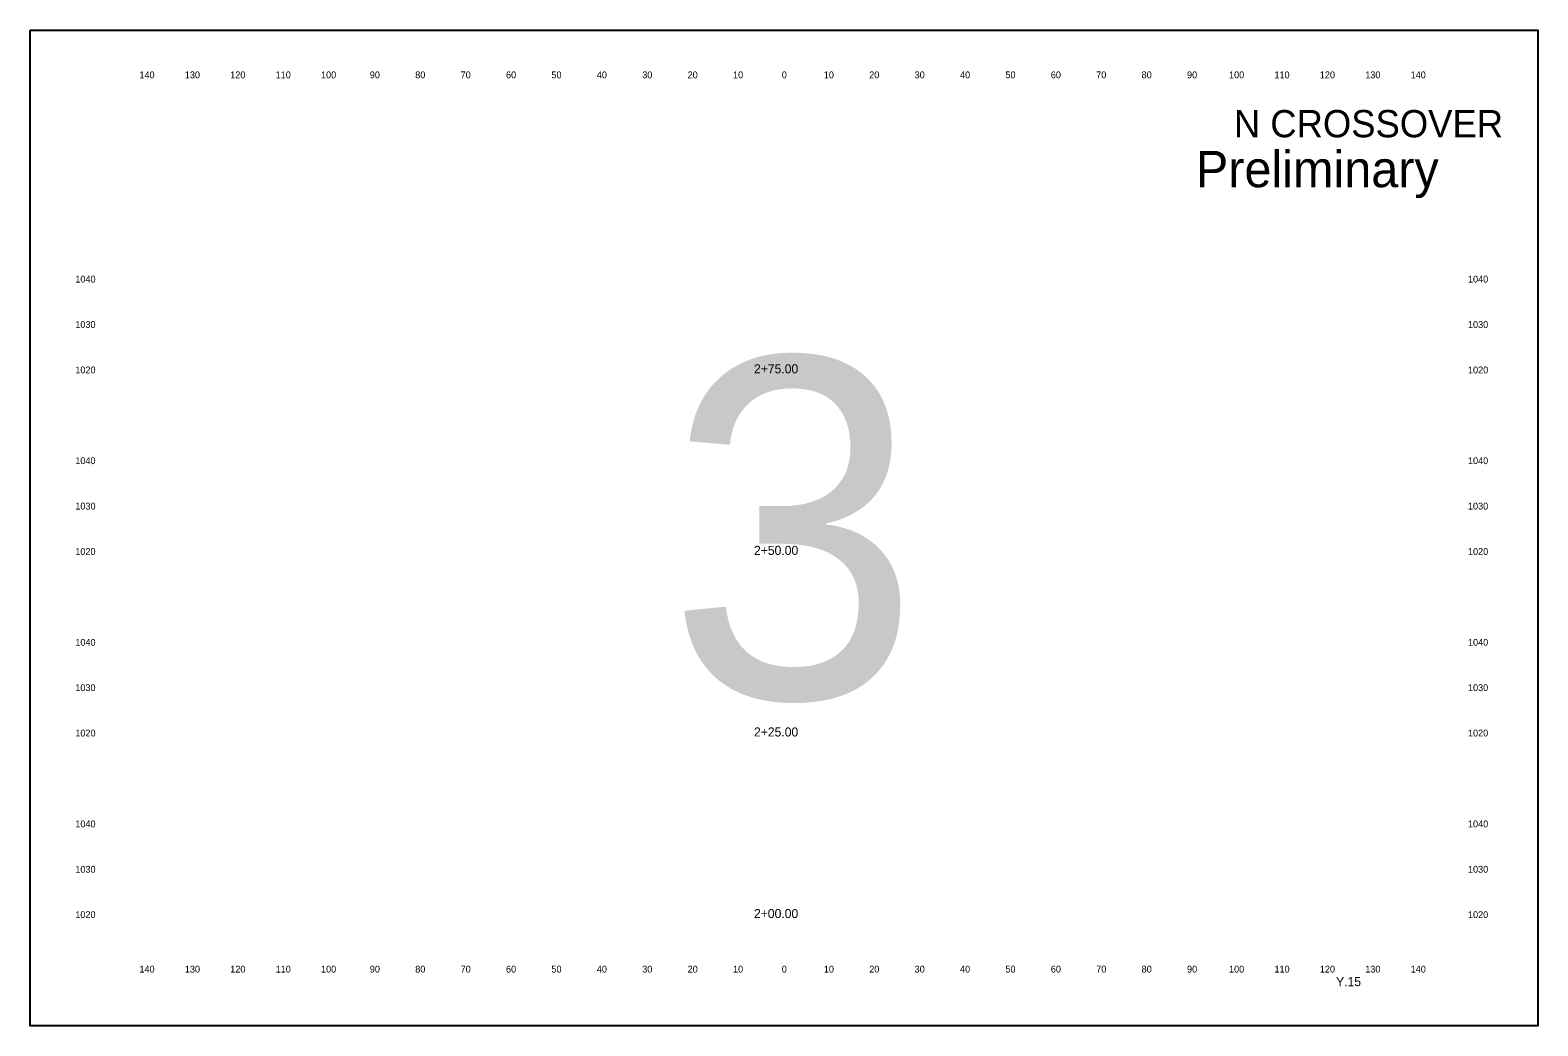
# Model space of a CAD drawing. Extents: x 10123 to 14767, y 9730 to 9950.
# Drawn here: x 10843.2 to 11175.3, y 9730.3 to 9949.6 of the extents above; entities that cross this region are included whole.
import ezdxf

# ---------------------------------------------------------------- set-up
doc = ezdxf.new("R2010")
doc.units = 0
for name, color, linetype in [('dsnTextCpn', 7, 'Continuous'), ('dsnTextCpnTitleSheetLocDesc', 7, 'Continuous'), ('dsnTextCpnTitleSheetPIN', 7, 'Continuous'), ('dsnTextCpnTitleSheetWorkType', 7, 'Continuous')]:
    doc.layers.add(name, color=color, linetype=linetype)

msp = doc.modelspace()

# ---------------------------------------------------------------- linework, layer by layer
at = {"layer": 'dsnTextCpnTitleSheetWorkType'}
msp.add_lwpolyline([(10843.21, 9949.6), (11175.29, 9949.6), (11175.29, 9730.26), (10843.21, 9730.26)], close=True, dxfattribs=at)

# ---------------------------------------------------------------- texts
at = {"layer": 'dsnTextCpn'}
for s, height, p in [('140', 1.5, (10867.27, 9939)), ('130', 1.5, (10877.27, 9939)), ('120', 1.5, (10887.27, 9939)), ('110', 1.5, (10897.27, 9939)), ('100', 1.5, (10907.27, 9939)), ('90', 1.5, (10918.02, 9939)), ('80', 1.5, (10928.02, 9939)), ('70', 1.5, (10938.02, 9939)), ('60', 1.5, (10948.02, 9939)), ('50', 1.5, (10958.02, 9939)), ('40', 1.5, (10968.02, 9939)), ('30', 1.5, (10978.02, 9939)), ('20', 1.5, (10988.02, 9939)), ('10', 1.5, (10998.02, 9939)), ('0', 1.5, (11008.76, 9939)), ('0', 1.5, (11008.76, 9939)), ('10', 1.5, (11018.02, 9939)), ('20', 1.5, (11028.02, 9939)), ('30', 1.5, (11038.02, 9939)), ('40', 1.5, (11048.02, 9939)), ('50', 1.5, (11058.02, 9939)), ('60', 1.5, (11068.02, 9939)), ('70', 1.5, (11078.02, 9939)), ('80', 1.5, (11088.02, 9939)), ('90', 1.5, (11098.02, 9939)), ('100', 1.5, (11107.27, 9939)), ('110', 1.5, (11117.27, 9939)), ('120', 1.5, (11127.27, 9939)), ('130', 1.5, (11137.27, 9939)), ('140', 1.5, (11147.27, 9939)), ('N CROSSOVER', 6, (11108.34, 9926)), ('1040', 1.5, (10853.15, 9894)), ('1040', 1.5, (11159.9, 9894)), ('1030', 1.5, (10853.15, 9884)), ('1030', 1.5, (11159.9, 9884)), ('1020', 1.5, (10853.15, 9874)), ('2+75.00', 2, (11002.64, 9874)), ('1020', 1.5, (11159.9, 9874)), ('1040', 1.5, (10853.15, 9854)), ('1040', 1.5, (11159.9, 9854)), ('1030', 1.5, (10853.15, 9844)), ('1030', 1.5, (11159.9, 9844)), ('1020', 1.5, (10853.15, 9834)), ('2+50.00', 2, (11002.64, 9834)), ('1020', 1.5, (11159.9, 9834)), ('1040', 1.5, (10853.15, 9814)), ('1040', 1.5, (11159.9, 9814)), ('1030', 1.5, (10853.15, 9804)), ('1030', 1.5, (11159.9, 9804)), ('1020', 1.5, (10853.15, 9794)), ('2+25.00', 2, (11002.64, 9794)), ('1020', 1.5, (11159.9, 9794)), ('1040', 1.5, (10853.15, 9774)), ('1040', 1.5, (11159.9, 9774)), ('1030', 1.5, (10853.15, 9764)), ('1030', 1.5, (11159.9, 9764)), ('1020', 1.5, (10853.15, 9754)), ('2+00.00', 2, (11002.64, 9754)), ('1020', 1.5, (11159.9, 9754)), ('140', 1.5, (10867.27, 9742)), ('130', 1.5, (10877.27, 9742)), ('120', 1.5, (10887.27, 9742)), ('110', 1.5, (10897.27, 9742)), ('100', 1.5, (10907.27, 9742)), ('90', 1.5, (10918.02, 9742)), ('80', 1.5, (10928.02, 9742)), ('70', 1.5, (10938.02, 9742)), ('60', 1.5, (10948.02, 9742)), ('50', 1.5, (10958.02, 9742)), ('40', 1.5, (10968.02, 9742)), ('30', 1.5, (10978.02, 9742)), ('20', 1.5, (10988.02, 9742)), ('10', 1.5, (10998.02, 9742)), ('0', 1.5, (11008.76, 9742)), ('0', 1.5, (11008.76, 9742)), ('10', 1.5, (11018.02, 9742)), ('20', 1.5, (11028.02, 9742)), ('30', 1.5, (11038.02, 9742)), ('40', 1.5, (11048.02, 9742)), ('50', 1.5, (11058.02, 9742)), ('60', 1.5, (11068.02, 9742)), ('70', 1.5, (11078.02, 9742)), ('80', 1.5, (11088.02, 9742)), ('90', 1.5, (11098.02, 9742)), ('100', 1.5, (11107.27, 9742)), ('110', 1.5, (11117.27, 9742)), ('120', 1.5, (11127.27, 9742)), ('130', 1.5, (11137.27, 9742)), ('140', 1.5, (11147.27, 9742))]:
    msp.add_text(s, height=height, dxfattribs=at).set_placement(p)
at = {"layer": 'dsnTextCpnTitleSheetLocDesc'}
msp.add_text('Preliminary', height=8, dxfattribs=at).set_placement((11099.97, 9915))
at = {"layer": 'dsnTextCpnTitleSheetPIN'}
msp.add_text('Y.15', height=2, dxfattribs=at).set_placement((11130.85, 9739))
at = {"layer": 'dsnTextCpnTitleSheetWorkType'}
msp.add_text('3', height=75, dxfattribs=at).set_placement((10983.48, 9802.43))

doc.saveas('drawing.dxf')
